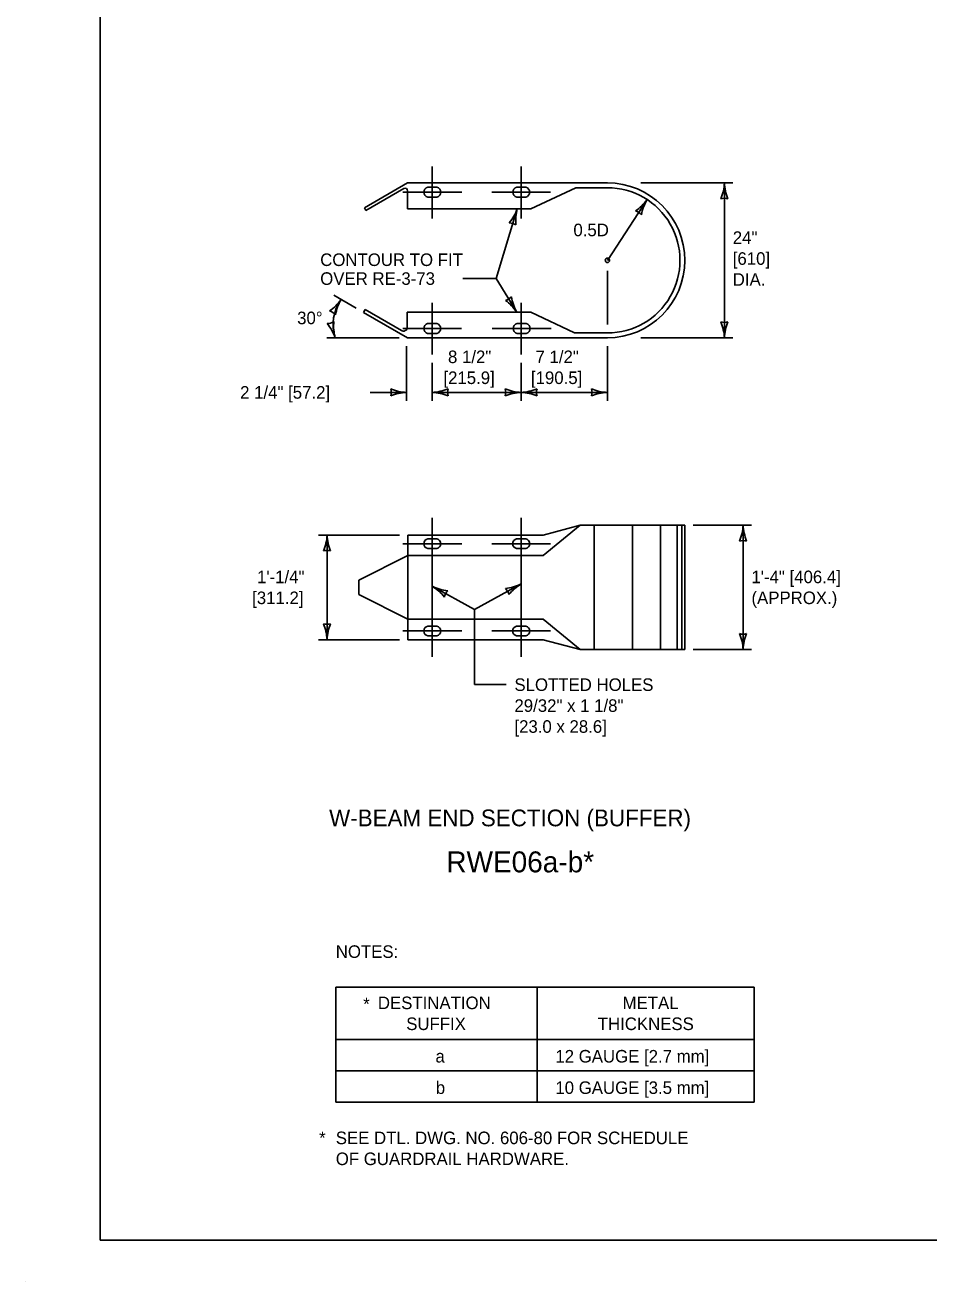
# Model space of a CAD drawing. Extents: x 49991.4 to 50021, y 49987.6 to 50011.4.
# Drawn here: x 49999.98 to 50004.3, y 49999.86 to 50005.87 of the extents above; entities that cross this region are included whole.
import ezdxf

# ---------------------------------------------------------------- set-up
doc = ezdxf.new("R2010")
doc.units = 0
for name, color, linetype in [('Level 1', 7, 'Continuous'), ('Level 2', 7, 'Continuous'), ('Level 3', 7, 'Continuous'), ('Level 5', 7, 'Continuous')]:
    doc.layers.add(name, color=color, linetype=linetype)

msp = doc.modelspace()

# ---------------------------------------------------------------- linework, layer by layer
at = {"layer": 'Level 1'}
for p, q in [((50001.8043, 50005.113), (50001.5977, 50004.9937)), ((50001.7866, 50005.0855), (50001.6052, 50004.9807)), ((50001.8043, 50005.113), (50002.7592, 50005.113)), ((50001.8043, 50004.9897), (50001.8043, 50005.0754)), ((50001.9007, 50005.0921), (50001.9444, 50005.0921)), ((50002.3257, 50005.0921), (50002.3694, 50005.0921)), ((50002.3931, 50004.9897), (50002.6085, 50005.0899)), ((50002.7592, 50005.0899), (50002.6085, 50005.0899)), ((50001.9444, 50005.0452), (50001.9007, 50005.0452)), ((50002.3694, 50005.0452), (50002.3257, 50005.0452)), ((50001.6052, 50004.9807), (50001.5977, 50004.9937)), ((50001.8043, 50004.9897), (50002.3931, 50004.9897)), ((50001.5937, 50004.4945), (50001.6013, 50004.5075)), ((50001.8043, 50004.373), (50001.5937, 50004.4945)), ((50001.7745, 50004.4075), (50001.6013, 50004.5075)), ((50001.8028, 50004.4958), (50002.3931, 50004.4958)), ((50001.8028, 50004.4958), (50001.8028, 50004.4234)), ((50002.3931, 50004.4958), (50002.602, 50004.3961)), ((50001.9439, 50004.4407), (50001.9002, 50004.4407)), ((50002.3275, 50004.4407), (50002.3712, 50004.4407)), ((50001.8043, 50004.373), (50002.7592, 50004.373)), ((50001.9002, 50004.3938), (50001.9439, 50004.3938)), ((50002.3712, 50004.3938), (50002.3275, 50004.3938)), ((50002.7592, 50004.3961), (50002.602, 50004.3961)), ((50002.4522, 50003.4306), (50002.6293, 50003.4777)), ((50002.4522, 50003.3323), (50002.6293, 50003.4777)), ((50002.6293, 50003.4777), (50003.1293, 50003.4777)), ((50002.6954, 50003.4777), (50002.6954, 50002.8835)), ((50002.8797, 50003.4777), (50002.8797, 50002.8835)), ((50003.0128, 50003.4777), (50003.0128, 50002.8835)), ((50003.0926, 50003.4777), (50003.0926, 50002.8835)), ((50003.1152, 50003.4777), (50003.1152, 50002.8835)), ((50003.1293, 50003.4777), (50003.1293, 50002.8835)), ((50001.8052, 50003.4306), (50002.4522, 50003.4306)), ((50001.8052, 50003.4306), (50001.8052, 50002.9306)), ((50001.9005, 50003.4125), (50001.9441, 50003.4125)), ((50002.3255, 50003.4125), (50002.3692, 50003.4125)), ((50001.5713, 50003.2142), (50001.8052, 50003.3323)), ((50001.8052, 50003.3323), (50002.4522, 50003.3323)), ((50001.9005, 50003.3656), (50001.9441, 50003.3656)), ((50002.3255, 50003.3656), (50002.3691, 50003.3656)), ((50001.5713, 50003.1469), (50001.5713, 50003.2142)), ((50001.5713, 50003.1469), (50001.8052, 50003.0288)), ((50001.8052, 50003.0288), (50002.4522, 50003.0288)), ((50002.4522, 50003.0288), (50002.6293, 50002.8835)), ((50001.9005, 50002.9956), (50001.9441, 50002.9956)), ((50002.3255, 50002.9956), (50002.3691, 50002.9956)), ((50001.8052, 50002.9306), (50002.4522, 50002.9306)), ((50001.9005, 50002.9487), (50001.9441, 50002.9487)), ((50002.3255, 50002.9487), (50002.3692, 50002.9487)), ((50002.4522, 50002.9306), (50002.6293, 50002.8835)), ((50002.6293, 50002.8835), (50003.1293, 50002.8835)), ((49999.9766, 49999.8624), (49999.9766, 49999.8624))]:
    msp.add_line(p, q, dxfattribs=at)
msp.add_lwpolyline([(50008.6146, 50011.2628), (50000.3356, 50011.2628), (50000.3356, 50000.0624), (50008.6146, 50000.0624)], close=True, dxfattribs=at)
for centre, radius, start, end in [((50001.7925, 50005.0753), 0.0118, 0, 119.85902), ((50001.906, 50005.0686), 0.024, 102.68209, 257.28785), ((50001.9391, 50005.0686), 0.024, 282.71525, 77.3148), ((50002.331, 50005.0686), 0.024, 102.68209, 257.28785), ((50002.3641, 50005.0686), 0.024, 282.71525, 77.3148), ((50002.759, 50004.743), 0.37, 270.02657, 89.97343), ((50002.7593, 50004.743), 0.3469, 269.98953, 90.01047), ((50001.7842, 50004.4234), 0.0186, 238.67979, 0), ((50001.9055, 50004.4173), 0.024, 102.71215, 257.31791), ((50001.9386, 50004.4173), 0.024, 282.6852, 77.28475), ((50002.3328, 50004.4173), 0.024, 102.71215, 257.31791), ((50002.3659, 50004.4173), 0.024, 282.6852, 77.28475), ((50001.9057, 50003.3891), 0.024, 102.71215, 257.31791), ((50001.9389, 50003.3891), 0.024, 282.6852, 77.28475), ((50002.3307, 50003.3891), 0.024, 102.71215, 257.31791), ((50002.3639, 50003.3891), 0.024, 282.6852, 77.28475), ((50001.9057, 50002.9721), 0.024, 102.68209, 257.28785), ((50001.9389, 50002.9721), 0.024, 282.71525, 77.3148), ((50002.3307, 50002.9721), 0.024, 102.68209, 257.28785), ((50002.3639, 50002.9721), 0.024, 282.71525, 77.3148)]:
    msp.add_arc(centre, radius, start, end, dxfattribs=at)
at = {"layer": 'Level 2'}
for p, q in [((50001.4611, 50001.2702), (50003.4611, 50001.2702)), ((50001.4611, 50001.2702), (50001.4611, 50000.7202)), ((50002.4244, 50001.2702), (50002.4244, 50000.7202)), ((50003.4611, 50001.2702), (50003.4611, 50000.7202)), ((50003.4611, 50001.0202), (50001.4611, 50001.0202)), ((50003.4611, 50000.8702), (50001.4611, 50000.8702)), ((50003.4611, 50000.7202), (50001.4611, 50000.7202))]:
    msp.add_line(p, q, dxfattribs=at)
at = {"layer": 'Level 3'}
for p, q in [((50002.9192, 50005.113), (50003.3584, 50005.113)), ((50003.3184, 50004.373), (50003.3184, 50005.113)), ((50002.7592, 50004.743), (50002.9491, 50005.0333)), ((50002.228, 50004.6559), (50002.3281, 50004.9897)), ((50002.0689, 50004.6559), (50002.228, 50004.6559)), ((50002.228, 50004.6559), (50002.3262, 50004.4958)), ((50002.7592, 50004.6925), (50002.7592, 50004.4361)), ((50001.5591, 50004.5145), (50001.4524, 50004.576)), ((50001.7643, 50004.373), (50001.4184, 50004.373)), ((50002.9192, 50004.373), (50003.3584, 50004.373)), ((50001.7996, 50004.333), (50001.7996, 50004.072)), ((50002.7592, 50004.333), (50002.7592, 50004.072)), ((50001.9219, 50004.2538), (50001.9219, 50004.072)), ((50002.3469, 50004.2538), (50002.3469, 50004.072)), ((50001.6262, 50004.112), (50001.7996, 50004.112)), ((50001.9219, 50004.112), (50002.3469, 50004.112)), ((50002.3469, 50004.112), (50002.7592, 50004.112)), ((50003.1693, 50003.4777), (50003.4478, 50003.4777)), ((50003.4078, 50002.8835), (50003.4078, 50003.4777)), ((50001.7652, 50003.4306), (50001.3794, 50003.4306)), ((50001.4194, 50002.9306), (50001.4194, 50003.4306)), ((50002.1236, 50003.0745), (50001.9219, 50003.1856)), ((50002.1236, 50003.0745), (50002.3469, 50003.1969)), ((50002.1236, 50002.7157), (50002.1236, 50003.0745)), ((50001.7652, 50002.9306), (50001.3794, 50002.9306)), ((50003.1693, 50002.8835), (50003.4478, 50002.8835)), ((50002.275, 50002.7157), (50002.1236, 50002.7157))]:
    msp.add_line(p, q, dxfattribs=at)
msp.add_circle((50002.7592, 50004.743), 0.0105, dxfattribs=at)
for centre, radius, start, end in [((50003.0963, 50005.1222), 0.2223, 337.45601, 357.63952), ((50003.5511, 50005.1245), 0.233, 182.82731, 202.07716), ((50002.7682, 50005.1626), 0.2223, 304.26308, 324.44658), ((50003.1502, 50004.9155), 0.233, 149.63438, 168.88423), ((50003.3184, 50004.9848), 0.0548, 72.13882, 107.86118), ((50002.118, 50005.0623), 0.2223, 320.76307, 340.94658), ((50002.5543, 50004.9339), 0.233, 166.13437, 185.38422), ((50002.8789, 50004.926), 0.0548, 38.94588, 74.66824), ((50002.2913, 50004.8669), 0.0548, 55.44588, 91.16824), ((50001.3062, 50004.6853), 0.2223, 304.26189, 324.4454), ((50001.6531, 50004.4362), 0.2047, 144.18951, 197.98966), ((50001.6881, 50004.4382), 0.233, 149.63319, 168.88304), ((50002.2592, 50004.6051), 0.0548, 283.66238, 319.38474), ((50002.1338, 50004.3643), 0.233, 34.35088, 53.60072), ((50002.5203, 50004.6041), 0.2223, 188.97958, 209.16308), ((50001.4169, 50004.4487), 0.0548, 38.9447, 74.66706), ((50001.4202, 50004.4954), 0.0548, 269.48206, 305.20442), ((50001.2397, 50004.2927), 0.233, 20.17055, 39.4204), ((50001.6732, 50004.4305), 0.2223, 174.79925, 194.98276), ((50003.3184, 50004.5012), 0.0548, 252.13882, 287.86118), ((50003.0857, 50004.3615), 0.233, 2.82731, 22.07716), ((50003.5405, 50004.3638), 0.2223, 157.45601, 177.63952), ((50001.8088, 50004.3341), 0.2223, 247.45601, 267.63952), ((50001.6714, 50004.112), 0.0548, 342.13882, 17.86118), ((50001.8111, 50003.8793), 0.233, 92.82731, 112.07716), ((50001.9104, 50004.3447), 0.233, 272.82731, 292.07716), ((50001.9127, 50003.8899), 0.2223, 67.45601, 87.63952), ((50002.0501, 50004.112), 0.0548, 162.13882, 197.86118), ((50002.3561, 50004.3341), 0.2223, 247.45601, 267.63952), ((50002.2187, 50004.112), 0.0548, 342.13882, 17.86118), ((50002.3584, 50003.8793), 0.233, 92.82731, 112.07716), ((50002.3354, 50004.3447), 0.233, 272.82731, 292.07716), ((50002.3377, 50003.8899), 0.2223, 67.45601, 87.63952), ((50002.4751, 50004.112), 0.0548, 162.13882, 197.86118), ((50002.7684, 50004.3341), 0.2223, 247.45601, 267.63952), ((50002.631, 50004.112), 0.0548, 342.13882, 17.86118), ((50002.7707, 50003.8793), 0.233, 92.82731, 112.07716), ((50003.1857, 50003.4869), 0.2223, 337.45601, 357.63952), ((50003.6405, 50003.4892), 0.233, 182.82731, 202.07716), ((50001.1973, 50003.4398), 0.2223, 337.45601, 357.63952), ((50001.6521, 50003.4421), 0.233, 182.82731, 202.07716), ((50003.4078, 50003.3495), 0.0548, 72.13882, 107.86118), ((50001.4194, 50003.3024), 0.0548, 72.13882, 107.86118), ((50001.8079, 50002.9947), 0.2223, 38.96336, 59.14687), ((50002.0228, 50003.3956), 0.233, 244.33466, 263.58451), ((50002.0346, 50003.1244), 0.0548, 133.64617, 169.36853), ((50002.2486, 50003.3963), 0.2223, 276.05012, 296.23363), ((50002.2343, 50003.1355), 0.0548, 10.73293, 46.45529), ((50002.4684, 50002.9981), 0.233, 121.42142, 140.67127), ((50001.4194, 50003.0588), 0.0548, 252.13882, 287.86118), ((50001.1867, 50002.9191), 0.233, 2.82731, 22.07716), ((50001.6415, 50002.9214), 0.2223, 157.45601, 177.63952), ((50003.4078, 50003.0117), 0.0548, 252.13882, 287.86118), ((50003.1751, 50002.872), 0.233, 2.82731, 22.07716), ((50003.6299, 50002.8743), 0.2223, 157.45601, 177.63952)]:
    msp.add_arc(centre, radius, start, end, dxfattribs=at)
at = {"layer": 'Level 5'}
for p, q in [((50001.9219, 50004.9434), (50001.9219, 50005.1921)), ((50002.3469, 50004.9434), (50002.3469, 50005.1921)), ((50001.782, 50005.0687), (50002.0631, 50005.0687)), ((50002.207, 50005.0687), (50002.4881, 50005.0687)), ((50001.9219, 50004.2938), (50001.9219, 50004.5407)), ((50002.3469, 50004.2938), (50002.3469, 50004.5407)), ((50001.7815, 50004.4173), (50002.0626, 50004.4173)), ((50002.2088, 50004.4173), (50002.4899, 50004.4173)), ((50001.9219, 50002.8487), (50001.9219, 50003.5125)), ((50002.3469, 50002.8487), (50002.3469, 50003.5125)), ((50001.7817, 50003.389), (50002.0629, 50003.389)), ((50002.2067, 50003.389), (50002.4879, 50003.389)), ((50001.7817, 50002.9721), (50002.0629, 50002.9721)), ((50002.2067, 50002.9721), (50002.4879, 50002.9721))]:
    msp.add_line(p, q, dxfattribs=at)

# ---------------------------------------------------------------- texts
at = {"layer": 'Level 2'}
for s, height, p in [('0.5D', 0.06, (50002.5968, 50004.8582)), ('24"', 0.06, (50003.3584, 50004.8216)), ('CONTOUR TO FIT', 0.06, (50001.3868, 50004.7159)), ('[610]', 0.06, (50003.3584, 50004.7216)), ('OVER RE-3-73', 0.06, (50001.3868, 50004.6259)), ('DIA.', 0.06, (50003.3584, 50004.6216)), ('30°', 0.06, (50001.2766, 50004.4379)), ('8 1/2"', 0.06, (50001.9975, 50004.252)), ('7 1/2"', 0.06, (50002.4159, 50004.252)), ('[215.9]', 0.06, (50001.9756, 50004.152)), ('[190.5]', 0.06, (50002.394, 50004.152)), ('2 1/4" [57.2]', 0.06, (50001.0041, 50004.082)), ('1\'-1/4"', 0.06, (50001.0849, 50003.2006)), ('1\'-4" [406.4]', 0.06, (50003.4478, 50003.2006)), ('[311.2]', 0.06, (50001.0615, 50003.1006)), ('(APPROX.)', 0.06, (50003.4478, 50003.1006)), ('SLOTTED HOLES', 0.06, (50002.315, 50002.6857)), ('29/32" x 1 1/8"', 0.06, (50002.315, 50002.5857)), ('[23.0 x 28.6]', 0.06, (50002.315, 50002.4857)), ('W-BEAM END SECTION (BUFFER)', 0.08, (50001.4293, 50002.039)), ('RWE06a-b*', 0.1, (50001.9897, 50001.819)), ('NOTES:', 0.06, (50001.4612, 50001.4103)), ('*', 0.06, (50001.5922, 50001.1597)), ('DESTINATION', 0.06, (50001.6624, 50001.1654)), ('METAL', 0.06, (50002.8319, 50001.1654)), ('SUFFIX', 0.06, (50001.7978, 50001.0654)), ('THICKNESS', 0.06, (50002.7131, 50001.0654)), ('a', 0.06, (50001.9376, 50000.9103)), ('12 GAUGE [2.7 mm]', 0.06, (50002.5106, 50000.9103)), ('b', 0.06, (50001.9393, 50000.7603)), ('10 GAUGE [3.5 mm]', 0.06, (50002.5106, 50000.7603)), ('*', 0.06, (50001.3816, 50000.5203)), ('SEE DTL. DWG. NO. 606-80 FOR SCHEDULE', 0.06, (50001.4612, 50000.5203)), ('OF GUARDRAIL HARDWARE.', 0.06, (50001.4612, 50000.4203))]:
    msp.add_text(s, height=height, dxfattribs=at).set_placement(p)

doc.saveas('drawing.dxf')
